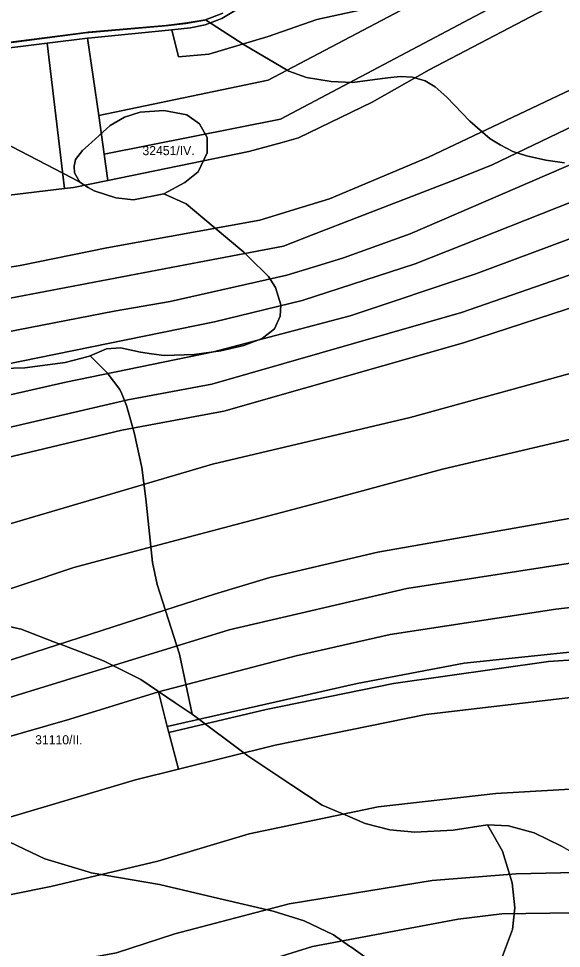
# Model space of a CAD drawing. Extents: x -535894 to -532834, y -1165802 to -1163645.
# Drawn here: x -535038 to -534740, y -1165071 to -1164561 of the extents above; entities that cross this region are included whole.
import ezdxf

# ---------------------------------------------------------------- set-up
doc = ezdxf.new("R2010")
doc.units = 0
for name, color, linetype in [('95560013', 7, 'Continuous'), ('95620013', 7, 'Continuous'), ('95640013', 7, 'Continuous'), ('95660013', 7, 'Continuous')]:
    doc.layers.add(name, color=color, linetype=linetype)

msp = doc.modelspace()

# ---------------------------------------------------------------- linework, layer by layer
at = {"layer": '95560013'}
for points in [[(-534836.85, -1164503.64), (-534832.14, -1164532.75), (-534822.67, -1164545.3), (-534830, -1164550.13), (-534845.17, -1164555.12), (-534874.58, -1164561.46), (-534901.23, -1164570.96), (-534933.74, -1164580.6), (-534950.39, -1164582.04), (-534954.11, -1164567.3), (-534943.8, -1164566.05), (-534935.73, -1164564.46), (-534926.58, -1164561.08), (-534915.74, -1164554.41), (-534905.82, -1164546.8), (-534892.07, -1164534.38)], [(-534768.01, -1164509.35), (-534755.68, -1164518.03), (-534901.21, -1164594.89), (-534994.2, -1164614.17), (-535000.27, -1164571.83), (-534999.95, -1164571.8), (-534954.11, -1164567.3), (-534950.39, -1164582.04), (-534933.74, -1164580.6), (-534901.23, -1164570.96), (-534874.58, -1164561.46), (-534845.17, -1164555.12), (-534830, -1164550.13), (-534822.67, -1164545.3)], [(-534755.68, -1164518.03), (-534749.42, -1164524.99), (-534743.38, -1164536.18), (-534894.51, -1164616.18), (-534991.15, -1164635.45), (-534994.2, -1164614.17), (-534901.21, -1164594.89)], [(-534743.38, -1164536.18), (-534737.42, -1164549.39), (-534812.95, -1164589.11), (-534844.16, -1164606.93), (-534884.64, -1164626.55), (-534893.57, -1164628.99), (-534911.75, -1164633.96), (-534989.09, -1164649.85), (-534991.15, -1164635.45), (-534894.51, -1164616.18)], [(-535022.48, -1164574.53), (-535012.94, -1164654.33), (-535060.19, -1164660.03), (-535071.3, -1164619.75), (-535083.39, -1164584.89), (-535054.91, -1164578.48)], [(-535000.27, -1164571.83), (-534994.2, -1164614.17), (-534991.15, -1164635.45), (-534989.09, -1164649.85), (-535007.94, -1164653.73), (-535012.94, -1164654.33), (-535022.48, -1164574.53)], [(-534710.3, -1164588.31), (-534700.55, -1164604.45), (-534706.29, -1164606.67), (-534778.34, -1164641.2), (-534797.89, -1164649.09), (-534877.44, -1164679.92), (-534892.83, -1164685.88), (-534939.12, -1164694.71), (-535062.16, -1164718.07), (-535065.86, -1164701.05), (-535037.23, -1164696.56), (-534989.77, -1164686.82), (-534905.84, -1164671.7), (-534882.51, -1164664.49), (-534867.62, -1164659.87), (-534813.38, -1164637)], [(-534706.29, -1164606.67), (-534700.55, -1164604.45), (-534690.65, -1164624.3), (-534694.91, -1164625.88), (-534731.01, -1164639.29), (-534823.37, -1164679.09), (-534859.96, -1164692.33), (-534872.36, -1164696.09), (-534891.05, -1164701.75), (-534954.93, -1164716.28), (-534985.67, -1164721.59), (-535058.34, -1164735.63), (-535062.16, -1164718.07), (-534939.12, -1164694.71), (-534892.83, -1164685.88), (-534877.44, -1164679.92), (-534797.89, -1164649.09), (-534778.34, -1164641.2)], [(-534690.65, -1164624.3), (-534680.75, -1164641.94), (-534685.32, -1164643.53), (-534716.28, -1164654.24), (-534820.53, -1164695.61), (-534882.6, -1164715.73), (-534930.6, -1164727.52), (-535229.64, -1164788.31), (-535234.09, -1164770.13), (-535204.83, -1164765.01), (-535150, -1164753.33), (-535058.34, -1164735.63), (-534985.67, -1164721.59), (-534954.93, -1164716.28), (-534891.05, -1164701.75), (-534872.36, -1164696.09), (-534859.96, -1164692.33), (-534823.37, -1164679.09), (-534731.01, -1164639.29), (-534694.91, -1164625.88)], [(-534685.32, -1164643.53), (-534680.75, -1164641.94), (-534669.21, -1164659.89), (-534675.43, -1164661.72), (-534705.37, -1164670.56), (-534787.37, -1164701.01), (-534856.21, -1164724.15), (-534931.28, -1164743.9), (-535012.13, -1164760.48), (-535158.6, -1164793.79), (-535225.1, -1164806.57), (-535229.64, -1164788.31), (-534930.6, -1164727.52), (-534882.6, -1164715.73), (-534820.53, -1164695.61), (-534716.28, -1164654.24)], [(-534669.21, -1164659.89), (-534657.84, -1164675.77), (-534662.44, -1164677.22), (-534691.34, -1164686.36), (-534795.22, -1164722.3), (-534932.16, -1164761.71), (-534978.25, -1164770.31), (-535087.47, -1164795.57), (-535217.32, -1164826.11), (-535225.1, -1164806.57), (-535158.6, -1164793.79), (-535012.13, -1164760.48), (-534931.28, -1164743.9), (-534856.21, -1164724.15), (-534787.37, -1164701.01), (-534705.37, -1164670.56), (-534675.43, -1164661.72)], [(-534662.44, -1164677.22), (-534657.84, -1164675.77), (-534648.21, -1164691.35), (-534794.04, -1164738.9), (-534925.58, -1164776.38), (-534981.55, -1164786.79), (-535087.94, -1164812.37), (-535210.21, -1164843.9), (-535217.32, -1164826.11), (-535087.47, -1164795.57), (-534978.25, -1164770.31), (-534932.16, -1164761.71), (-534795.22, -1164722.3), (-534691.34, -1164686.36)], [(-534644.26, -1164706.72), (-534642.29, -1164732.8), (-534729.01, -1164753.95), (-534823.37, -1164779.94), (-534931.7, -1164805.53), (-535046.65, -1164839.34), (-535194.99, -1164879.49), (-535210.21, -1164843.9), (-535087.94, -1164812.37), (-534981.55, -1164786.79), (-534925.58, -1164776.38), (-534794.04, -1164738.9), (-534648.21, -1164691.35)], [(-534729.01, -1164753.95), (-534642.29, -1164732.8), (-534639.25, -1164772.83), (-534705.71, -1164784.93), (-534805.56, -1164808.33), (-534871.85, -1164826.25), (-534989.4, -1164857.3), (-535007.79, -1164862.16), (-535095.84, -1164891.7), (-535170.48, -1164913.86), (-535177.9, -1164919.08), (-535185.4, -1164901.91), (-535194.99, -1164879.49), (-535046.65, -1164839.34), (-534931.7, -1164805.53), (-534823.37, -1164779.94)], [(-534639.25, -1164772.83), (-534637.67, -1164793.79), (-534635.77, -1164799.17), (-534633.72, -1164804.95), (-534638.54, -1164823.25), (-534671.88, -1164825.83), (-534710.47, -1164830.87), (-534729.94, -1164834.28), (-534841.03, -1164853.81), (-534900.4, -1164867.67), (-534930.69, -1164876.79), (-534980.06, -1164892.73), (-535115.81, -1164936.57), (-535159.15, -1164946.66), (-535170.48, -1164913.86), (-535095.84, -1164891.7), (-535007.79, -1164862.16), (-534989.4, -1164857.3), (-534871.85, -1164826.25), (-534805.56, -1164808.33), (-534705.71, -1164784.93)], [(-534729.94, -1164834.28), (-534710.47, -1164830.87), (-534705.37, -1164856.07), (-534723.79, -1164857.99), (-534825.11, -1164873.81), (-534922.64, -1164896.44), (-535101.94, -1164951.67), (-535154.63, -1164965.06), (-535159.15, -1164946.66), (-535115.81, -1164936.57), (-534980.06, -1164892.73), (-534930.69, -1164876.79), (-534900.4, -1164867.67), (-534841.03, -1164853.81)], [(-534705.37, -1164856.07), (-534641.49, -1164849.43), (-534643.23, -1164857.71), (-534659.18, -1164861.96), (-534703.62, -1164873.54), (-534701.97, -1164880.31), (-534743.37, -1164885.15), (-534834.28, -1164898.95), (-534885.94, -1164910.64), (-534961.47, -1164930.35), (-535010.08, -1164945.35), (-535149.32, -1164985.4), (-535151, -1164981.54), (-535154.63, -1164965.06), (-535101.94, -1164951.67), (-534922.64, -1164896.44), (-534825.11, -1164873.81), (-534723.79, -1164857.99)], [(-534743.37, -1164885.15), (-534701.97, -1164880.31), (-534695.57, -1164904.53), (-534793.82, -1164914.8), (-534852.33, -1164925.8), (-534956.54, -1164949.5), (-534961.47, -1164930.35), (-534885.94, -1164910.64), (-534834.28, -1164898.95)], [(-534695.57, -1164904.53), (-534694, -1164910.49), (-534703.82, -1164910.78), (-534747.53, -1164913.81), (-534832.45, -1164925.81), (-534902.3, -1164940.2), (-534955.68, -1164952.84), (-534956.54, -1164949.5), (-534852.33, -1164925.8), (-534793.82, -1164914.8)], [(-534694, -1164910.49), (-534659.5, -1164909.46), (-534659.02, -1164930.05), (-534691.31, -1164930.67), (-534736.79, -1164933.73), (-534814.82, -1164942.8), (-534897.39, -1164959.74), (-534950.5, -1164972.92), (-534955.68, -1164952.84), (-534902.3, -1164940.2), (-534832.45, -1164925.81), (-534747.53, -1164913.81), (-534703.82, -1164910.78)], [(-534961.47, -1164930.35), (-534956.54, -1164949.5), (-534955.68, -1164952.84), (-534950.5, -1164972.92), (-534974.01, -1164978.76), (-535073.21, -1165008.15), (-535132.68, -1165021.61), (-535138.71, -1165009.74), (-535149.32, -1164985.4), (-535010.08, -1164945.35)], [(-534691.31, -1164930.67), (-534659.02, -1164930.05), (-534658.67, -1164944.77), (-534658.09, -1164968.25), (-534657.76, -1164976.32), (-534659.02, -1164979.39), (-534688.38, -1164981.11), (-534776.34, -1164986.27), (-534840.9, -1164993.6), (-534911.68, -1165008.4), (-534961.7, -1165023.3), (-535020.48, -1165037.2), (-535106.82, -1165054.65), (-535109.11, -1165052.7), (-535117.6, -1165047.48), (-535124.68, -1165038.88), (-535132.68, -1165021.61), (-535073.21, -1165008.15), (-534974.01, -1164978.76), (-534950.5, -1164972.92), (-534897.39, -1164959.74), (-534814.82, -1164942.8), (-534736.79, -1164933.73)], [(-534688.38, -1164981.11), (-534659.02, -1164979.39), (-534659.81, -1164981.95), (-534655.57, -1165032.56), (-534724.66, -1165029.47), (-534765.23, -1165030.38), (-534811.29, -1165033.87), (-534889.63, -1165046.79), (-534952.44, -1165063.23), (-534984.36, -1165073.72), (-535013.06, -1165078.91), (-535040.34, -1165080.81), (-535067.25, -1165085.28), (-535068.17, -1165084.42), (-535089.33, -1165069.61), (-535106.82, -1165054.65), (-535020.48, -1165037.2), (-534961.7, -1165023.3), (-534911.68, -1165008.4), (-534840.9, -1164993.6), (-534776.34, -1164986.27)], [(-534765.23, -1165030.38), (-534724.66, -1165029.47), (-534655.57, -1165032.56), (-534654.53, -1165060.65), (-534677.01, -1165058.08), (-534733.66, -1165051.62), (-534773.14, -1165052.16), (-534797.08, -1165055.15), (-534876.98, -1165070.12), (-534985.58, -1165103.95), (-535010.28, -1165108.81), (-535038.78, -1165114.13), (-535054.81, -1165096.75), (-535067.25, -1165085.28), (-535040.34, -1165080.81), (-535013.06, -1165078.91), (-534984.36, -1165073.72), (-534952.44, -1165063.23), (-534889.63, -1165046.79), (-534811.29, -1165033.87)]]:
    msp.add_lwpolyline(points, close=True, dxfattribs=at)
for points in [[(-535060.19, -1164660.03), (-535012.94, -1164654.33), (-535007.94, -1164653.73), (-534989.09, -1164649.85), (-534911.75, -1164633.96), (-534893.57, -1164628.99), (-534884.64, -1164626.55), (-534844.16, -1164606.93), (-534812.95, -1164589.11), (-534737.42, -1164549.39), (-534720.94, -1164570.71), (-534717.56, -1164576.29), (-534710.3, -1164588.31), (-534813.38, -1164637), (-534867.62, -1164659.87), (-534882.51, -1164664.49), (-534905.84, -1164671.7), (-534989.77, -1164686.82), (-535037.23, -1164696.56), (-535065.86, -1164701.05)], [(-534985.58, -1165103.95), (-534876.98, -1165070.12), (-534797.08, -1165055.15), (-534773.14, -1165052.16), (-534733.66, -1165051.62), (-534677.01, -1165058.08), (-534654.53, -1165060.65), (-534656.31, -1165088.09)]]:
    msp.add_lwpolyline(points, dxfattribs=at)
at = {"layer": '95620013'}
msp.add_lwpolyline([(-534926.03, -1164558.08), (-534936.2, -1164561.96), (-534946.31, -1164563.69), (-534957.79, -1164565.07), (-535001.64, -1164568.89), (-535054.61, -1164575.73), (-535101.2, -1164586.14), (-535117.95, -1164592.03), (-535326.28, -1164371.53)], dxfattribs=at)
at = {"layer": '95640013'}
for points in [[(-534915.74, -1164554.41), (-534926.58, -1164561.08), (-534935.73, -1164564.46), (-534943.8, -1164566.05), (-534954.11, -1164567.3), (-534999.95, -1164571.8), (-535000.27, -1164571.83), (-535022.48, -1164574.53), (-535054.91, -1164578.48)], [(-535054.61, -1164575.73), (-535001.64, -1164568.89), (-534957.79, -1164565.07), (-534946.31, -1164563.69), (-534936.2, -1164561.96), (-534926.03, -1164558.08)]]:
    msp.add_lwpolyline(points, dxfattribs=at)
at = {"layer": '95660013'}
for points in [[(-534930.369, -1164559.695), (-534935.616, -1164561.701), (-534945.728, -1164563.423), (-534957.21, -1164564.802), (-535000, -1164568.532), (-535001.057, -1164568.625), (-535054.023, -1164575.458), (-535100.616, -1164585.868), (-535112.034, -1164589.882), (-535117.371, -1164591.759), (-535121.179, -1164593.097), (-535123.817, -1164594.021), (-535156.991, -1164608.077), (-535174.047, -1164617.688), (-535225.782, -1164662.124), (-535264.558, -1164694.259), (-535273.775, -1164699.521), (-535285.222, -1164705.064), (-535292.152, -1164708.42), (-535298.828, -1164711.653), (-535321.651, -1164717.756), (-535337.207, -1164722.574), (-535394.549, -1164753.205), (-535432.662, -1164773.563)], [(-534738.7, -1164640.23), (-534748.89, -1164638.76), (-534759.578, -1164636.363), (-534767.01, -1164633.94), (-534773.98, -1164630.4), (-534779.43, -1164626.97), (-534790.62, -1164617.29), (-534803.2, -1164604.15), (-534809.571, -1164598.54), (-534815.11, -1164595.27), (-534822.08, -1164593.24), (-534828.79, -1164592.798), (-534835.54, -1164593.629), (-534842.78, -1164594.52), (-534855.05, -1164596.03), (-534866.6, -1164595.63), (-534880.29, -1164593.32), (-534889.93, -1164589.82), (-534914.46, -1164575.48), (-534935.616, -1164561.701), (-534930.369, -1164559.695)], [(-535054.023, -1164575.458), (-535001.057, -1164568.625), (-535000, -1164568.532), (-534957.21, -1164564.802), (-534945.728, -1164563.423), (-534935.616, -1164561.701), (-534914.46, -1164575.48), (-534889.93, -1164589.82), (-534880.29, -1164593.32), (-534866.6, -1164595.63), (-534855.05, -1164596.03), (-534842.78, -1164594.52), (-534835.54, -1164593.629), (-534828.79, -1164592.798), (-534822.08, -1164593.24), (-534815.11, -1164595.27), (-534809.571, -1164598.54), (-534803.2, -1164604.15), (-534790.62, -1164617.29), (-534779.43, -1164626.97), (-534773.98, -1164630.4), (-534767.01, -1164633.94), (-534759.578, -1164636.363), (-534748.89, -1164638.76), (-534738.7, -1164640.23)], [(-534740.289, -1165015.17), (-534755.42, -1165007.85), (-534769.44, -1165004.02), (-534780.901, -1165003.39), (-534799.7, -1165006.25), (-534820.808, -1165007.363), (-534834.58, -1165006.09), (-534847.96, -1165002.59), (-534857.787, -1164998.444), (-534871.542, -1164992.642), (-534888.74, -1164981.25), (-534912.31, -1164965.64), (-534942.953, -1164942.645), (-534949.821, -1164909.73), (-534962.081, -1164871.5), (-534964.71, -1164859.4), (-534968.3, -1164824.6), (-534970.61, -1164807.39), (-534974.75, -1164788.119), (-534978.97, -1164773.39), (-534981.555, -1164767.006), (-534982.55, -1164764.55), (-534989.56, -1164755.47), (-534998.88, -1164746.15), (-534989.88, -1164742.17), (-534982.23, -1164741.77), (-534971.32, -1164744.08), (-534965.241, -1164744.9), (-534958.34, -1164745.83), (-534941.78, -1164745.43), (-534927.119, -1164743.28), (-534914.62, -1164740.34), (-534904.579, -1164736.52), (-534897.74, -1164731.34), (-534894.71, -1164724.25), (-534894.31, -1164718.04), (-534897.26, -1164708.64), (-534901, -1164702.59), (-534911.817, -1164691.901), (-534914.54, -1164689.21), (-534931.42, -1164675.19), (-534946.24, -1164662.77), (-534958.5, -1164657.23), (-534946.87, -1164651.02), (-534939.55, -1164645.13), (-534934.767, -1164634.758), (-534934.723, -1164626.253), (-534938.91, -1164618.851), (-534945.817, -1164613.887), (-534958.5, -1164611.52), (-534971.375, -1164612.361), (-534980, -1164615.18), (-534987.81, -1164619.8), (-535000.001, -1164630.658), (-535003.1, -1164633.42), (-535006.837, -1164638.361), (-535007.72, -1164642.02), (-535007.4, -1164645.77), (-535004.53, -1164650.86), (-535008.91, -1164648.51), (-535046.58, -1164628.92)], [(-535046.58, -1164628.92), (-535008.91, -1164648.51), (-535004.53, -1164650.86), (-535000, -1164653.636), (-534996.73, -1164655.64), (-534984.78, -1164659.461), (-534975.07, -1164660.42), (-534958.5, -1164657.23), (-534946.24, -1164662.77), (-534931.42, -1164675.19), (-534914.54, -1164689.21), (-534911.817, -1164691.901), (-534901, -1164702.59), (-534897.26, -1164708.64), (-534894.31, -1164718.04), (-534894.71, -1164724.25), (-534897.74, -1164731.34), (-534904.579, -1164736.52), (-534914.62, -1164740.34), (-534927.119, -1164743.28), (-534941.78, -1164745.43), (-534958.34, -1164745.83), (-534965.241, -1164744.9), (-534971.32, -1164744.08), (-534982.23, -1164741.77), (-534989.88, -1164742.17), (-534998.88, -1164746.15), (-535000.001, -1164746.447), (-535012.66, -1164749.811), (-535034.79, -1164752.68), (-535065.7, -1164753.639)], [(-535065.7, -1164753.639), (-535034.79, -1164752.68), (-535012.66, -1164749.811), (-535000.001, -1164746.447), (-534998.88, -1164746.15), (-534989.56, -1164755.47), (-534982.55, -1164764.55), (-534981.555, -1164767.006), (-534978.97, -1164773.39), (-534974.75, -1164788.119), (-534970.61, -1164807.39), (-534968.3, -1164824.6), (-534964.71, -1164859.4), (-534962.081, -1164871.5), (-534949.821, -1164909.73), (-534942.953, -1164942.645), (-534952.19, -1164936.387), (-534971.08, -1164923.59), (-534991.541, -1164913.492), (-535000, -1164910.221), (-535015.68, -1164904.16), (-535015.961, -1164904.051), (-535036.71, -1164896.031), (-535055.17, -1164892.088)], [(-535055.17, -1164892.088), (-535036.71, -1164896.031), (-535015.961, -1164904.051), (-535015.68, -1164904.16), (-535000, -1164910.221), (-534991.541, -1164913.492), (-534971.08, -1164923.59), (-534952.19, -1164936.387), (-534942.953, -1164942.645), (-534912.31, -1164965.64), (-534888.74, -1164981.25), (-534871.542, -1164992.642), (-534857.787, -1164998.444), (-534847.96, -1165002.59), (-534834.58, -1165006.09), (-534820.808, -1165007.363), (-534799.7, -1165006.25), (-534780.901, -1165003.39), (-534772.78, -1165017.8), (-534767.37, -1165035.32), (-534765.93, -1165048.861), (-534767.212, -1165060.767), (-534772.62, -1165075.46)], [(-534772.62, -1165075.46), (-534767.212, -1165060.767), (-534765.93, -1165048.861), (-534767.37, -1165035.32), (-534772.78, -1165017.8), (-534780.901, -1165003.39), (-534769.44, -1165004.02), (-534755.42, -1165007.85), (-534740.289, -1165015.17), (-534716.24, -1165028.71), (-534705.33, -1165033.01), (-534690.75, -1165036.2), (-534668.45, -1165039.7), (-534623.879, -1165046.695), (-534577.061, -1165054.045), (-534549.471, -1165060.17), (-534517.62, -1165071), (-534482.42, -1165079.6)], [(-534848.201, -1165075.82), (-534855.909, -1165070.372), (-534856.575, -1165069.901), (-534865.357, -1165063.694), (-534881.49, -1165056.07), (-534898.543, -1165050.818), (-534928.32, -1165043.8), (-534960.879, -1165036.126), (-534998.24, -1165029.79), (-535000, -1165029.25), (-535023.73, -1165021.98), (-535034.832, -1165016.773), (-535051.92, -1165008.759)], [(-535051.92, -1165008.759), (-535034.832, -1165016.773), (-535023.73, -1165021.98), (-535000, -1165029.25), (-534998.24, -1165029.79), (-534960.879, -1165036.126), (-534928.32, -1165043.8), (-534898.543, -1165050.818), (-534881.49, -1165056.07), (-534865.357, -1165063.694), (-534856.575, -1165069.901), (-534855.909, -1165070.372), (-534848.201, -1165075.82)]]:
    msp.add_lwpolyline(points, dxfattribs=at)
msp.add_lwpolyline([(-534958.5, -1164657.23), (-534975.07, -1164660.42), (-534984.78, -1164659.461), (-534996.73, -1164655.64), (-535000, -1164653.636), (-535004.53, -1164650.86), (-535007.4, -1164645.77), (-535007.72, -1164642.02), (-535006.837, -1164638.361), (-535003.1, -1164633.42), (-535000.001, -1164630.658), (-534987.81, -1164619.8), (-534980, -1164615.18), (-534971.375, -1164612.361), (-534958.5, -1164611.52), (-534945.817, -1164613.887), (-534938.91, -1164618.851), (-534934.723, -1164626.253), (-534934.767, -1164634.758), (-534939.55, -1164645.13), (-534946.87, -1164651.02)], close=True, dxfattribs=at)

# ---------------------------------------------------------------- texts
msp.add_text('32451/IV.', height=5, rotation=360, dxfattribs=at).set_placement((-534970.177, -1164635.97))
msp.add_text('31110/II.', height=5, dxfattribs=at).set_placement((-535029.041, -1164959.242))

doc.saveas('drawing.dxf')
